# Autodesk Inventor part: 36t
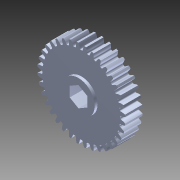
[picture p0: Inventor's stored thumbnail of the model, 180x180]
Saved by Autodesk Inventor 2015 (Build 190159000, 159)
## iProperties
Created: 2014-11
Part Number: 36t
Material: Aluminum 6061
Document SubType Name: Modeling
Designer: Michael
Density: 2.71 g/cm^3
Appearance: Aluminum - Flat
Title: 217-3213-STEP.STEP
Description: STEP AP214
Creation Date: 2013-12-09
Sending System: SolidWorks 2013
Preprocessor: SwSTEP 2.0
Author: Michael
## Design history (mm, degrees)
node "36t1"
node "Cut-Extrude2"
node "Base1"
